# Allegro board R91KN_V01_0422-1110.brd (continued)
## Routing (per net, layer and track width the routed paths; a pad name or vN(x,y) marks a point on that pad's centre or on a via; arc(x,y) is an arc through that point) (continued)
M_MDA43: length 67.1
  TOP w0.1: 102.61,64.01 101.96,64.01 101.82,63.87 101.48,63.87 101.43,63.91 100.71,63.91 100.69,63.88 100.39,63.88 100.37,63.91 99.92,63.91 99.88,63.88 99.12,63.88 98.65,63.4 U1.F11
  TOP w0.12: v1(126.71,67.43) 126.69,67.43 126.69,67.41 126.18,67.93 126.18,70.57 126.3,70.69 127.46,70.69 127.58,70.81 127.58,71.24 127.46,71.36 124.06,71.36 123.94,71.49 123.94,72.07 124.06,72.19 124.79,72.19 124.8,72.2 124.8,72.19 126.03,72.19 126.16,72.32 126.16,72.55 126.03,72.67 124.79,72.67 124.68,72.79 124.68,73.03 124.8,73.16 125.84,73.16 125.96,73.28 125.96,73.54 125.84,73.67 124.88,73.67 124.75,73.79 124.75,74.1 124.88,74.22 126.05,74.22 126.18,74.35 126.18,74.53 126.03,74.68 124.32,74.68 124.2,74.56 124.2,73.01 124,72.8 123.79,72.8 123.52,72.53 123.52,70.83 123.1,70.41 111.98,70.41 109.54,67.98 109.54,67.92 107.47,65.86 104.77,65.86 102.91,64.01 102.61,64.01
  BOTTOM w0.12: v1(126.71,67.43) 126.69,67.43 126.69,67.41 126.37,67.41 126.25,67.52 126.25,67.74 126.24,67.75 126.24,70.56 126.63,70.96 v4(126.63,71.34) 126.63,72 126.94,72.3 130.5,72.3 131.22,73.02 132.71,73.02 132.92,73.23 132.92,73.43 133.29,73.8 133.48,73.8 133.5,73.82 133.51,73.82 133.72,74.03 133.72,74.03 133.86,74.17 U402.H7
M_MDA44: length 65.7
  TOP w0.099: 102.58,65.33 102.34,65.09 101.04,65.09 U1.A9
  TOP w0.12: v1(109.78,70.34) 107.17,67.74 107.16,67.74 107.01,67.59 105.15,67.59 102.88,65.33 102.58,65.33
  BOTTOM w0.12: 137.37,76.58 137.5,76.58 137.94,77.02 138.31,77.02 138.52,77.23 138.52,77.43 138.82,77.73 139.34,77.73 139.59,77.99 139.67,77.99 140.34,78.65 140.34,80.46 135.69,85.11 122.65,85.11 121.45,83.91 121.45,81.78 119.51,79.85 117.09,79.85 116.76,79.53 114.59,77.39 114.52,77.34 114.38,77.2 114.06,77.05 113.76,76.85 112.99,76.53 112.17,76.36 112.16,76.36 112.12,76.32 110.61,76.32 110.05,75.75 110.05,75.53 110.17,75.41 v4(110.59,75.41) 110.59,75.41 110.71,75.29 110.71,75.05 110.59,74.93 110.17,74.93 110.05,74.81 110.05,74.58 110.17,74.45 110.59,74.45 110.59,74.45 110.71,74.33 110.71,74.09 110.59,73.97 110.17,73.97 110.05,73.84 110.05,73.63 110.17,73.5 110.56,73.5 110.67,73.39 110.67,73.2 110.56,73.08 109.55,73.08 109.45,72.98 109.45,72.71 109.57,72.58 111.09,72.58 111.22,72.46 111.22,71.06 110.49,70.34 v1(109.78,70.34)
M_MDA45: length 66
  TOP w0.099: U1.C9 100.4,65.25 100.66,65.25
  TOP w0.12: 100.66,65.25 100.68,65.27 100.77,65.27 100.82,65.33 101.09,65.33 101.09,65.32 102.24,65.32 102.56,65.64 102.89,65.64 105.23,67.99 105.66,67.99 105.66,67.98 106.62,67.98 106.89,68.26 106.89,68.42 106.84,68.48 106.84,68.65 107,68.82 107.17,68.82 107.23,68.76 107.4,68.76 107.57,68.93 107.57,69.1 107.51,69.16 107.51,69.33 107.68,69.5 107.85,69.5 107.91,69.44 108.08,69.44 v4(108.25,69.61) 108.25,69.78 108.19,69.84 108.19,70.01 108.34,70.16 109.03,70.16 109.37,70.49 109.37,70.51 109.6,70.75 109.62,70.75 109.85,70.98 110.1,70.98 110.28,70.81 v1(110.3,70.81)
  BOTTOM w0.12: v1(110.3,70.81) 110.06,71.05 109.89,71.05 109.06,71.88 109.06,73.36 109.18,73.48 109.53,73.48 109.65,73.6 109.65,73.84 109.53,73.96 109.17,73.96 109.06,74.08 109.06,74.32 109.17,74.44 109.53,74.44 109.65,74.56 109.65,74.8 109.53,74.92 109.17,74.92 109.06,75.04 109.06,75.31 110.5,76.76 112.13,76.76 112.87,76.9 113.57,77.19 113.94,77.44 114.18,77.57 114.25,77.64 114.35,77.7 116.73,80.05 116.93,80.25 119.35,80.25 121.05,81.95 121.05,84.11 122.45,85.5 135.85,85.5 140.56,80.8 140.56,77.49 140.15,77.09 139.8,77.09 139.32,76.61 139.32,76.43 139.11,76.22 138.61,76.22 U402.F2
M_MDA46: length 66.6
  TOP w0.099: 103.07,66.12 105.14,68.19 ; 102.39,66.13 102.22,66.13 102.12,66.04 102.12,65.66 102,65.53 101.18,65.53 101.18,65.53 100.73,65.53 100.68,65.49 100.13,65.49 100.01,65.36 100.01,65.32 99.88,65.19 99.62,65.19 99.48,65.33 99.22,65.33 99.09,65.19 98.67,65.19 98.55,65.07 U1.F9
  TOP w0.1: 103.07,66.12 102.8,65.86 102.61,65.86 102.48,65.98 102.48,66.04 102.39,66.13
  TOP w0.12: v1(109,71.33) 108.95,71.33 108.29,70.66 108.09,70.66 107.85,70.42 107.85,70.22 107.61,69.98 107.41,69.98 107.17,69.75 107.17,69.54 106.93,69.3 106.73,69.3 106.49,69.07 106.49,68.86 v4(106.18,68.55) 106.01,68.38 105.8,68.38 105.79,68.36 105.47,68.36 105.45,68.38 105.32,68.38 105.14,68.19
  BOTTOM w0.12: v1(109,71.33) 108.85,71.33 108.59,71.58 108.59,75.41 110.33,77.15 112.09,77.15 112.76,77.28 113.39,77.54 113.82,77.83 114.1,78.01 116.63,80.5 116.77,80.64 119.19,80.64 120.66,82.11 120.66,84.29 122.27,85.89 136.01,85.89 140.95,80.96 140.95,77.32 140.57,76.95 140.57,76.72 140.78,76.52 140.78,75.96 140.17,75.35 139.81,75.35 139.75,75.41 138.6,75.41 U402.G2
M_MDA47: length 65.9
  TOP w0.099: U1.D8 100.03,66.08 100.37,66.08 100.39,66.11 100.68,66.11 100.71,66.09 101.17,66.09 101.41,66.33 102.86,66.33 105.29,68.76 105.56,68.76
  TOP w0.12: 105.56,68.76 107.82,71.03 107.89,71.03 107.94,71.07 107.96,71.07 108.03,71.14 v1(108.19,71.14)
  BOTTOM w0.12: 137.37,74.17 137.6,74.17 137.96,74.54 139.91,74.54 141.34,75.97 141.34,81.12 136.41,86.05 136.41,86.06 136.18,86.29 121.97,86.29 119.91,84.24 v4(119.91,83.21) 119.91,81.92 119.03,81.03 116.6,81.03 113.86,78.32 113.7,78.22 113.2,77.89 112.64,77.66 112.05,77.54 110.16,77.54 108.19,75.57 v1(108.19,71.14)
M_MDA48: length 67.3
  TOP w0.099: 100.74,67.14 100.55,66.94 100.38,66.94 100.19,67.13 99.94,67.13 99.78,66.97 99.78,66.72 99.65,66.6 U1.E7 ; 101.12,67.14 101.43,67.14 101.53,67.23
  TOP w0.1: 100.74,67.14 101.12,67.14
  TOP w0.12: 101.53,67.23 102.14,67.23 102.27,67.36 102.27,68.39 104.9,71.02 104.9,72.06 105.63,72.78 105.63,75.05 105.73,75.16 106.06,75.16 106.18,75.03 106.18,73.2 106.32,73.06 106.52,73.06 106.66,73.2 106.66,73.2 106.66,75.03 106.78,75.16 107.02,75.16 107.14,75.03 107.14,73.2 107.28,73.06 107.48,73.06 107.62,73.2 107.62,73.2 107.62,75.05 107.75,75.18 107.97,75.18 108.1,75.05 108.1,73.2 108.24,73.06 108.31,73.06 108.32,73.06 108.45,73.06 108.58,73.2 108.58,73.2 108.58,75.03 108.7,75.16 108.78,75.16 108.8,75.18 108.94,75.18 109.06,75.05 109.06,73.2 109.19,73.06 109.41,73.06 109.54,73.2 109.54,73.2 109.54,75.03 109.66,75.16 109.89,75.16 110.02,75.03 110.02,73.2 110.16,73.06 110.65,73.06 110.77,73.18 110.77,73.36 110.5,73.62 110.5,75.03 110.62,75.16 110.87,75.16 110.99,75.03 110.99,73.7 111.13,73.56 111.28,73.56 111.47,73.75 111.47,75.03 111.6,75.16 112.37,75.16 112.78,75.56 112.78,76.27 113.01,76.5 113.36,76.5 v4(116.82,79.96) 117.17,80.31 117.99,80.31 118.55,80.87 118.59,80.87 118.61,80.89 118.62,80.89 118.63,80.9 133.13,80.9 133.15,80.89 133.33,80.89 133.38,80.83 133.39,80.83 134.12,80.11 134.12,79.93 134.16,79.88 U401.A3
M_MDA49: length 66.6
  TOP w0.1: U1.A7 101.08,66.73 101.08,66.73 102.51,66.73 104.09,68.31
  TOP w0.12: 133.37,79.78 133.37,79.99 133.23,80.12 132.72,80.12 132.71,80.13 132.42,80.13 132.41,80.12 131.92,80.12 131.91,80.13 131.49,80.13 131.41,80.05 131.41,79.77 131.37,79.72 130.83,79.72 130.71,79.85 130.71,79.88 130.58,80 130.09,80 129.9,79.81 129.73,79.81 129.54,80 129.37,80 129.18,79.81 129.01,79.81 128.82,80 128.65,80 128.46,79.81 128.29,79.81 128.1,80 127.93,80 127.74,79.81 127.57,79.81 127.38,80 127.21,80 127.02,79.81 126.78,79.81 126.65,79.94 126.65,79.94 126.53,80.07 126,80.07 125.88,79.94 125.88,79.13 125.76,79.02 125.52,79.02 125.4,79.14 125.4,79.97 125.27,80.09 125.04,80.09 124.92,79.97 124.92,79.13 124.8,79.02 124.56,79.02 124.44,79.14 124.44,79.97 124.31,80.09 124.08,80.09 123.96,79.97 123.96,79.13 123.84,79.02 123.6,79.02 123.48,79.14 123.48,79.97 123.35,80.09 123.12,80.09 123,79.97 123,79.13 122.88,79.02 122.64,79.02 122.52,79.14 122.52,79.97 122.39,80.09 122.16,80.09 122.04,79.97 122.04,79.13 121.92,79.02 121.69,79.02 121.57,79.14 121.57,79.97 121.45,80.09 121.18,80.09 121.06,79.97 121.06,79.12 120.94,79 120.53,79 120.41,79.12 v4(120.41,79.75) 120.41,79.91 120.28,80.03 119.48,80.03 119.36,79.91 119.36,79.77 119.63,79.5 119.73,79.5 119.86,79.38 119.86,79.19 119.72,79.05 119.54,79.05 119.33,79.26 119.15,79.26 119,79.11 119,78.93 119.61,78.31 119.61,78.14 119.44,77.97 119.27,77.97 118.65,78.59 118.48,78.59 118.31,78.42 118.31,78.25 118.93,77.63 118.93,77.46 118.76,77.29 118.59,77.29 117.97,77.91 117.8,77.91 117.63,77.74 117.63,77.57 118.25,76.95 118.25,76.78 118.08,76.61 117.91,76.61 117.29,77.23 117.12,77.23 116.95,77.06 116.95,76.89 117.58,76.27 117.58,76.1 117.41,75.94 117.24,75.94 116.62,76.56 116.45,76.56 116.28,76.39 116.28,76.22 116.9,75.6 116.9,75.43 116.73,75.26 116.56,75.26 115.94,75.88 115.77,75.88 115.6,75.71 115.6,75.54 116.22,74.92 116.22,74.75 116.05,74.58 115.88,74.58 115.26,75.2 114.89,75.2 114.42,74.72 114.42,74.7 114.09,74.37 114.09,74.19 114.53,73.75 114.53,72.71 114.1,72.28 108.64,72.28 108.64,72.28 106.43,72.28 106.31,72.15 106.31,72 106.12,71.82 105.96,71.82 105.94,71.84 105.8,71.84 105.69,71.73 105.69,70.69 104.09,69.09 104.09,68.31
M_MDA50: length 67.1
  TOP w0.1: U1.C7 100.21,66.54 100.51,66.54 100.63,66.67 100.63,66.73 100.81,66.92 100.94,66.92 100.96,66.93 102.43,66.93 103.46,67.96 103.46,69.02
  TOP w0.12: 103.46,69.02 105.29,70.86 105.29,71.89 106.07,72.67 108.48,72.67 108.48,72.67 111.73,72.67 111.85,72.8 v4(111.85,73.09) 111.85,73.58 111.87,73.59 111.87,74.61 111.99,74.73 112.36,74.73 112.48,74.61 112.48,74.6 112.88,74.2 112.88,73.96 112.48,73.56 112.48,72.79 112.6,72.67 112.88,72.67 113,72.8 113,73.51 113.13,73.64 113.43,73.64 113.56,73.51 113.56,72.8 113.68,72.67 113.93,72.67 114.09,72.83 114.09,73.43 114.1,73.44 114.1,73.61 112.82,74.88 112.82,75.05 112.99,75.22 113.16,75.22 113.68,74.7 113.86,74.7 114.02,74.86 114.02,75.04 113.25,75.81 113.25,75.98 113.38,76.11 113.63,76.11 114.35,75.39 114.53,75.39 114.69,75.55 114.69,75.73 114.02,76.39 114.02,76.57 114.19,76.73 114.36,76.73 114.95,76.15 115.12,76.15 115.29,76.31 115.29,76.49 114.68,77.1 114.68,77.26 114.85,77.44 115.02,77.44 115.66,76.79 115.84,76.79 116,76.95 116,77.13 115.38,77.75 115.38,77.93 115.54,78.09 115.72,78.09 116.37,77.44 116.55,77.44 116.71,77.6 116.71,77.78 116.02,78.47 116.02,78.61 116.22,78.81 116.36,78.81 117.12,78.05 117.29,78.05 117.46,78.22 117.46,78.39 116.89,78.96 116.89,79.11 117.08,79.3 117.23,79.3 117.78,78.75 117.96,78.75 118.12,78.91 118.12,79.09 117.57,79.64 117.57,79.79 117.7,79.92 117.97,79.92 118.52,79.37 118.7,79.37 118.86,79.53 118.86,79.71 118.51,80.06 118.51,80.23 118.78,80.5 132.97,80.5 132.98,80.5 133.17,80.5 133.5,80.17 133.5,80.17 133.72,79.95 133.72,78.89 134.16,78.44 U401.C3
M_MDA51: length 67.7
  TOP w0.099: 99.34,66.28 99.48,66.28 99.48,66.29 100.28,66.29 100.3,66.3
  TOP w0.1: U1.F7 98.5,66.65 98.5,66.86 98.4,66.97 98.19,66.97 98.07,66.84 98.07,66.41 98.19,66.28 99.34,66.28 ; 108.13,71.74 108.12,71.74 107.91,71.53 107.88,71.53 107.8,71.45 107.78,71.45 107.73,71.41 107.52,71.41 107.47,71.45 107.46,71.45 107.23,71.69 107.23,71.7 107.04,71.89 106.86,71.89 106.74,71.77 106.74,71.63 107.24,71.13 107.24,70.99 107.09,70.84 106.95,70.84 106.36,71.44 106.2,71.44 106.08,71.32 106.08,71.15 106.67,70.56 106.67,70.42 106.53,70.28 106.39,70.28 106.22,70.44 106.05,70.44 105.94,70.33 105.94,70.16 106.1,70 106.1,69.85 105.96,69.71 105.82,69.71 105.61,69.93 105.46,69.93 105.32,69.79 105.32,69.65 105.54,69.43 105.54,69.29 105.4,69.15 105.26,69.15 105.04,69.36 104.9,69.36 104.76,69.22 104.76,69.08 104.97,68.86 104.97,68.72 102.78,66.53 101.33,66.53 101.09,66.28 100.81,66.28 100.79,66.31 100.31,66.31 100.3,66.3
  TOP w0.12: 108.13,71.74 108.27,71.88 114.25,71.88 114.92,72.55 114.92,74.48 115.02,74.58 115.32,74.58 115.45,74.44 115.45,74.14 115.58,74.02 116.04,74.02 119.6,77.57 119.77,77.57 120.33,77 120.51,77 120.67,77.17 120.67,77.34 120,78.01 120,78.2 v4(120.28,78.48) 120.4,78.6 120.97,78.6 121.11,78.46 121.11,77.27 121.23,77.15 121.47,77.15 121.59,77.27 121.59,77.27 121.59,78.46 121.72,78.58 121.94,78.58 122.07,78.46 122.07,77.27 122.19,77.15 122.43,77.15 122.55,77.27 122.55,77.27 122.55,78.46 122.68,78.58 122.91,78.58 123.03,78.46 123.03,77.27 123.15,77.15 123.39,77.15 123.51,77.27 123.51,77.27 123.51,78.46 123.63,78.58 123.87,78.58 123.99,78.46 123.99,77.27 124.11,77.15 124.35,77.15 124.47,77.27 124.47,77.27 124.47,78.46 124.59,78.58 124.82,78.58 124.95,78.46 124.95,77.27 125.07,77.15 125.31,77.15 125.43,77.27 125.43,77.27 125.43,78.46 125.56,78.58 125.78,78.58 125.91,78.46 125.91,77.27 126.03,77.15 126.22,77.15 126.4,77.33 126.81,77.73 129.93,77.73 130.22,78.03 131.08,78.03 131.47,78.42 131.47,78.9 131.63,79.06 131.82,79.06 132.06,78.83 132.06,78.75 132.19,78.62 133.62,78.62 133.73,78.52 133.73,78.3 133.6,78.17 133.37,78.17
M_MDA52: length 66.2
  TOP w0.12: U1.A5 101.16,68.2 102.44,69.48 102.44,69.5 102.68,69.74 102.68,70.09 102.8,70.22 103.03,70.22 103.16,70.34 103.16,70.52 103.05,70.62 102.84,70.62 102.72,70.75 102.72,70.9 102.93,71.12 103.25,71.12 103.44,71.31 103.44,71.62 103.44,72.1 104.16,72.82 104.16,77.41 104.44,77.68 104.44,77.85 104.16,78.13 104.16,78.36 104.3,78.5 104.47,78.5 104.78,78.19 104.95,78.19 107.83,81.07 107.83,81.24 107.75,81.32 107.75,81.5 107.91,81.66 108.09,81.66 108.17,81.58 108.42,81.58 110.62,83.77 112.94,83.77 113.06,83.65 113.06,83.45 113.2,83.31 113.37,83.31 113.38,83.31 113.4,83.31 113.53,83.43 113.53,83.65 113.65,83.77 113.88,83.77 114,83.65 114,82.68 114.21,82.47 114.35,82.47 114.48,82.59 114.48,83.65 114.59,83.77 114.84,83.77 114.96,83.65 114.96,82.45 114.65,82.14 114.65,81.89 114.79,81.76 114.96,81.76 115.11,81.91 115.11,81.91 115.44,82.24 115.44,83.65 115.55,83.77 115.8,83.77 115.92,83.65 115.92,83.23 116.04,83.11 116.27,83.11 116.4,83.23 116.4,83.67 116.5,83.77 134.42,83.77 134.52,83.67 134.52,83.53 134.64,83.41 134.87,83.41 135,83.53 135,83.67 135.09,83.77 135.51,83.77 135.79,83.5 135.79,83.33 v4(135.34,82.87) 135.34,82.7 135.5,82.54 135.68,82.54 136.13,82.99 136.3,82.99 136.47,82.82 136.47,82.65 136.02,82.2 136.02,82.02 136.18,81.86 136.36,81.86 136.81,82.31 136.98,82.31 137.15,82.14 137.15,81.97 136.62,81.44 136.62,81.26 136.78,81.1 136.96,81.1 137.47,81.61 137.64,81.61 138.01,81.24 138.01,81.06 137.77,80.83 137.43,80.83 137.3,80.7 137.3,80.46 137.43,80.33 137.7,80.33 137.82,80.21 137.82,79.9 137.71,79.78 137.59,79.78 137.59,79.78 137.37,79.78
M_MDA53: length 66.7
  TOP w0.1: 99.35,68.44 99.53,68.62 100.79,68.62
  TOP w0.12: U1.E5 99.35,68.44 ; 100.79,68.62 101.21,68.62 102.39,69.8 102.39,71.17 103.09,71.86 103.09,72.49 103.77,73.17 103.77,79 104.07,79.31 104.24,79.31 104.79,78.76 104.96,78.76 105.13,78.93 105.13,79.1 104.58,79.64 104.58,79.81 104.75,79.98 104.92,79.98 105.47,79.44 105.64,79.44 105.81,79.61 105.81,79.78 105.26,80.32 105.26,80.49 105.43,80.66 105.6,80.66 106.15,80.11 106.32,80.11 106.49,80.28 106.49,80.45 105.94,81 105.94,81.17 106.11,81.34 106.28,81.34 106.74,80.88 106.92,80.88 107.08,81.05 107.08,81.22 106.62,81.68 106.62,81.85 106.79,82.02 106.96,82.02 107.22,81.76 107.39,81.76 107.56,81.93 107.56,82.1 107.3,82.36 107.3,82.53 107.47,82.7 107.64,82.7 108.19,82.15 108.36,82.15 108.53,82.32 108.53,82.49 107.98,83.04 107.98,83.21 108.15,83.38 108.32,83.38 108.87,82.83 109.04,82.83 109.21,83 109.21,83.17 108.66,83.72 108.66,83.89 108.93,84.17 109.16,84.17 109.29,84.04 109.29,83.66 109.41,83.53 109.75,83.53 109.88,83.66 v4(109.88,83.95) 109.88,84.04 110,84.17 135.67,84.17 138.98,80.86 138.98,80.44 138.66,80.11 138.66,79.97 138.53,79.85 138.53,79.29 138.22,78.97 U401.B8
M_MDA54: length 66.2
  TOP w0.1: 101.73,70.28 101.72,70.27 101.72,70.27 100.81,69.37 100.8,69.37 100.58,69.16 100.58,69.05 100.45,68.92 100.23,68.92 U1.C3
  TOP w0.12: 101.73,70.28 101.86,70.41 101.86,71.08 102.82,72.05 102.82,73.16 v4(103.19,73.52) 103.38,73.71 103.38,74.09 103.25,74.21 102.6,74.21 102.47,74.09 102.47,73.8 102.35,73.67 102.07,73.67 101.94,73.8 101.94,74.57 102.07,74.69 103.25,74.69 103.38,74.82 103.38,75.19 103.25,75.32 103.25,75.32 101.42,75.32 101.31,75.42 101.31,75.7 101.4,75.79 103.24,75.79 103.38,75.93 103.38,76.2 103.25,76.33 102.82,76.33 102.69,76.45 102.69,76.69 102.82,76.81 103.25,76.81 103.25,76.81 103.38,76.94 103.38,77.21 103.25,77.33 102.88,77.33 102.76,77.46 102.76,77.69 102.88,77.81 103.25,77.81 103.38,77.94 103.38,78.28 103.14,78.51 103.14,78.66 103.38,78.9 103.38,79.16 108.77,84.56 135.84,84.56 139.46,80.93 139.56,80.93 139.8,80.69 139.8,80.35 139.32,79.87 139.32,79.55 139.41,79.45 139.59,79.45 139.62,79.42 139.75,79.42 139.87,79.3 139.87,79 139.75,78.88 139.41,78.88 139.15,78.62 139.04,78.62 138.94,78.53 138.82,78.53 138.61,78.32 138.61,78.17 138.48,78.04 138.29,78.04 138.16,78.17 U401.C8
M_MDA55: length 66.1
  TOP w0.12: U1.E1 99.48,69.94 99.48,70.09 100.44,71.06 100.62,71.06 100.8,71.22 101.18,71.22 102.28,72.32 102.28,72.73 102.16,72.86 101.72,72.86 101.53,73.04 101.53,74.65 100.92,75.27 100.92,75.69 100.8,75.81 100.6,75.81 100.48,75.69 100.48,74.92 100.35,74.8 100.17,74.8 100.05,74.92 100.05,75.89 100.22,76.05 100.22,76.06 100.34,76.18 100.34,76.21 100.38,76.26 100.38,76.5 100.5,76.62 100.75,76.62 100.86,76.5 100.86,76.31 100.98,76.18 102.12,76.18 102.25,76.31 102.25,76.54 102.12,76.66 101.42,76.66 101.3,76.79 101.3,76.96 101.35,77.02 101.35,77.02 101.48,77.14 102,77.14 v4(102.16,77.31) 102.28,77.42 102.28,77.88 102.74,78.34 102.74,79.08 108.61,84.95 136,84.95 140.12,80.83 140.12,78.43 139.74,78.06 139.67,78.06 139.34,77.73 138.31,77.73 138.02,77.73 137.81,77.52 137.81,77.28 137.69,77.15 137.49,77.15 137.37,77.28 137.37,77.38
M_MDA56: length 65
  TOP w0.1: 99.35,69.33 99.23,69.33 98.87,68.96 98.87,68.36 98.22,67.71 98.22,67.42 97.75,66.95 U1.G7
  TOP w0.12: v1(100.97,70.81) 100.95,70.83 100.54,70.83 99.7,70 99.7,69.68 99.35,69.33 ; v1(115.37,73.36) 115.41,73.33 v4(115.41,72.14) 115.41,72 115.53,71.88 116.73,71.88 116.94,72.09 116.94,72.27 117.17,72.5 117.17,72.75 117.3,72.88 117.85,72.88 118.31,73.33 118.31,73.36 118.6,73.66 118.61,73.66 119.98,75.03 121.31,75.03 121.45,75.16 126.53,75.16 126.69,75 126.69,74.28 126.57,74.17 126.57,72.42 126.69,72.3 129.18,72.3 129.43,72.55 129.43,72.79 129.72,73.08 130.11,73.08 130.13,73.11 130.98,73.11 131.01,73.14 131.83,73.14 132.51,73.82 132.71,73.82 132.92,74.03 132.92,74.23 133.22,74.53 133.62,74.53 133.97,74.17 U401.H3
  BOTTOM w0.12: v1(115.37,73.36) 114.47,73.36 114.34,73.24 114.34,72.94 114.22,72.81 114,72.81 113.88,72.94 113.88,73.31 113.72,73.47 113.39,73.47 113.27,73.34 113.27,69.13 112.7,68.56 112.7,68.56 112.47,68.33 112.47,68.33 112.29,68.16 112.12,68.16 111.95,68.33 111.7,68.33 111.57,68.2 111.57,68.03 111.78,67.82 111.78,67.65 111.61,67.48 111.44,67.48 111.39,67.53 111.09,67.53 110.96,67.41 110.96,67.16 110.98,67.14 110.98,66.84 110.81,66.67 110.54,66.67 110.41,66.8 110.41,67.14 110.29,67.27 110,67.27 109.86,67.13 109.86,66.59 110.03,66.42 110.03,66.2 109.91,66.08 109.51,66.08 109.38,66.2 109.39,67.19 109.27,67.31 109.03,67.31 108.91,67.18 108.91,66.2 108.78,66.08 108.55,66.08 108.42,66.2 108.43,67.19 108.31,67.31 108.07,67.31 107.94,67.18 107.94,66.2 107.82,66.08 107.59,66.08 107.47,66.2 107.47,67.19 107.35,67.31 107.1,67.31 106.97,67.17 106.97,66.2 106.84,66.08 106.63,66.08 106.5,66.2 106.5,68.2 106.38,68.33 104.11,68.33 101.76,70.68 101.1,70.68 v1(100.97,70.81)
M_MDA57: length 64.6
  TOP w0.099: 98.28,69.6 98.15,69.47 98.15,68.14 97.75,67.74 U1.G6
  TOP w0.12: 133.37,74.97 133.34,74.97 132.93,74.56 130.41,74.56 v4(129.69,75.28) 129.41,75.56 121.29,75.56 121.16,75.42 119.82,75.42 118.45,74.06 118.44,74.06 117.91,73.53 117.91,73.5 117.69,73.28 116.9,73.28 116.78,73.15 116.78,72.66 116.65,72.53 116.24,72.53 116.12,72.66 116.12,73.31 116.08,73.34 v1(116.08,73.36) ; 98.28,69.6 98.28,70.02 98.26,70.03 98.26,70.78 98.33,70.85 ; 98.74,71.4 99.4,72.06 100.27,72.06 v1(100.31,72.03)
  TOP w0.13: 98.74,71.4 98.33,70.99 98.33,70.85
  BOTTOM w0.12: v1(100.31,72.03) 100.31,71.78 100.79,71.3 101.72,71.3 103.62,69.4 103.79,69.4 104.05,69.66 104.22,69.66 104.39,69.49 104.39,69.32 104.13,69.06 104.13,68.89 104.3,68.72 104.84,68.72 104.96,68.84 104.96,69.53 105.09,69.66 105.32,69.66 105.44,69.53 105.44,68.84 105.56,68.72 105.8,68.72 105.92,68.84 105.92,69.45 106.05,69.58 106.25,69.58 106.4,69.42 106.4,68.84 106.52,68.72 106.55,68.72 106.55,68.72 106.78,68.72 106.9,68.59 106.9,67.8 107,67.7 107.21,67.7 107.31,67.8 107.31,68.59 107.44,68.72 107.61,68.72 107.73,68.59 107.73,67.79 107.83,67.7 108.04,67.7 108.13,67.79 108.13,68.59 108.25,68.72 108.49,68.72 108.61,68.59 108.61,67.84 108.73,67.72 108.96,67.72 109.09,67.84 109.09,68.59 109.21,68.72 109.45,68.72 109.57,68.59 109.57,67.85 109.69,67.72 109.9,67.72 110.05,67.87 110.05,68.59 110.17,68.72 110.41,68.72 110.53,68.59 110.53,67.99 110.65,67.87 110.89,67.87 111.01,67.99 111.01,68.6 111.13,68.72 112.31,68.72 112.87,69.29 112.87,73.19 112.49,73.57 112.49,74.64 112.6,74.75 112.84,74.75 112.94,74.64 112.94,73.99 113.07,73.87 113.31,73.87 113.43,73.98 113.43,74.61 113.56,74.73 113.78,74.73 113.91,74.61 113.91,73.93 114.03,73.8 115.64,73.8 v1(116.08,73.36)
M_MDA58: length 63.7
  TOP w0.099: U1.G1 97.75,70.45 97.79,70.49
  TOP w0.12: v1(117.06,74.38) 117.16,74.38 117.19,74.34 117.62,74.34 119.5,76.22 120,76.22 120,76.22 120.83,76.22 120.95,76.34 130.03,76.34 130.16,76.47 130.16,76.49 130.28,76.61 130.28,76.64 130.41,76.77 130.99,76.77 131.12,76.64 131.12,76.58 131.37,76.33 131.49,76.33 131.6,76.22 133.51,76.22 133.86,76.58 U401.E3 ; v1(101.13,72.46) 100.8,72.79 100.8,72.86 100.53,73.12 99.83,73.12 97.79,71.07 97.79,70.49
  BOTTOM w0.12: v1(101.13,72.46) 101.56,72.03 102.67,72.03 104.56,73.92 v4(104.56,74.49) 105.04,74.98 107.25,74.98 107.37,74.85 107.37,74.62 107.25,74.5 105.29,74.5 105.16,74.37 105.16,73.62 105.28,73.5 105.48,73.5 105.61,73.63 105.61,73.89 105.73,74.02 107.24,74.02 107.37,73.89 107.37,73.66 107.24,73.54 106.13,73.54 106.01,73.42 106.01,73.18 106.13,73.06 107.16,73.06 107.28,72.93 107.28,72.8 106.88,72.4 106.65,72.4 106.41,72.64 106.23,72.64 106.08,72.49 106.08,72.31 106.3,72.09 106.3,71.82 106.13,71.65 106.13,70.8 106.36,70.57 107.42,69.52 111.22,69.52 112.09,70.39 112.09,72.87 111.71,73.25 111.71,75.16 112.08,75.53 113.33,75.53 113.64,75.84 114.55,75.84 114.69,75.7 114.69,74.83 114.91,74.61 116.84,74.61 117.06,74.41 v1(117.06,74.38)
M_MDA59: length 64.1
  TOP w0.099: U1.G3 97.92,69.17 97.92,69.53 98.06,69.67 98.06,69.93 98.04,69.96 98.04,70.42
  TOP w0.12: v1(100.39,72.69) 100.38,72.69 100.35,72.71 99.73,72.71 98.04,71.01 98.04,70.42 ; 133.37,75.78 133.01,75.42 131.63,75.42 131.17,74.96 130.81,74.96 129.82,75.95 121.12,75.95 120.99,75.82 119.84,75.82 119.84,75.83 119.66,75.83 118.29,74.45 118.28,74.45 117.5,73.67 116.87,73.67 116.71,73.83 116.65,73.83 116.63,73.84 v1(116.6,73.84)
  BOTTOM w0.12: v1(100.39,72.69) 100.72,72.36 100.72,72.18 101.32,71.58 101.89,71.58 102.07,71.4 102.24,71.4 102.48,71.64 102.83,71.64 102.84,71.65 102.85,71.65 102.92,71.58 102.92,71.4 102.58,71.06 102.58,70.89 102.75,70.72 102.92,70.72 103.37,71.18 103.55,71.18 103.71,71.01 103.71,70.84 103.26,70.38 103.26,70.21 103.41,70.06 104.06,70.06 104.18,70.18 104.18,71.52 104.06,71.64 103.35,71.64 103.23,71.76 103.23,72 103.35,72.12 104.06,72.12 104.18,72.24 104.18,72.98 104.35,73.15 104.56,73.15 104.68,73.03 104.68,70.18 104.81,70.06 105.01,70.06 105.13,70.18 105.13,72.92 105.26,73.05 105.49,73.05 105.62,72.92 105.62,72.92 105.62,70.18 105.74,70.06 106.32,70.06 107.26,69.12 111.38,69.12 112.48,70.22 112.48,73.03 112.1,73.41 112.1,74.83 112.41,75.14 113.49,75.14 113.57,75.22 v4(114.06,75.22) 114.14,75.22 114.3,75.07 114.3,74.37 114.44,74.22 115.06,74.22 115.09,74.19 116.34,74.19 116.58,73.95 116.58,73.89 116.6,73.88 v1(116.6,73.84)
M_MDA60: length 68.1
  TOP w0.099: 96.52,70.85 96.51,70.84 96.51,70.18 96.66,70.03 96.66,70.02 96.66,70.02 96.66,69.59 96.62,69.55 96.62,69.29 96.7,69.2 96.7,68.81 96.66,68.77 96.66,68.75 96.62,68.72 96.62,68.61 96.47,68.45 96.47,67.97 96.37,67.86 95.81,67.86 95.69,67.74 95.69,67.53 95.81,67.4 U1.J6
  TOP w0.12: 137.37,75.78 137.6,75.78 137.81,75.99 138.04,76.22 138.37,76.22 138.49,76.34 138.49,76.4 138.52,76.43 138.52,76.72 138.49,76.75 138.49,76.89 138.62,77.02 139.11,77.02 139.16,77.06 139.7,77.06 139.73,77.09 139.79,77.09 139.87,77.17 139.93,77.17 140.18,77.41 140.18,77.61 140.38,77.81 140.38,81.13 136.16,85.34 108.36,85.34 102.11,79.09 102.11,78.92 102.35,78.68 102.35,78.5 102.19,78.34 102.01,78.34 101.77,78.58 101.6,78.58 101.43,78.41 101.43,78.24 101.68,77.99 101.68,77.82 101.52,77.66 101.34,77.66 101.09,77.9 100.92,77.9 100.75,77.73 100.75,77.57 100.96,77.36 100.96,77.18 100.8,77.02 100.62,77.02 100.41,77.23 100.24,77.23 99.96,76.95 99.96,76.42 99.95,76.41 99.02,75.47 99.02,75.47 98.62,75.06 98.61,75.06 97.66,74.12 97.66,73.8 v4(97.56,73.7) 97.07,73.21 97.07,71.4 96.52,70.85
M_MDA61: length 67.1
  TOP w0.099: 96.49,72.55 96.1,71.24 96.1,69.85 U1.J1
  TOP w0.12: 137.37,74.17 137.12,74.17 136.99,74.3 136.99,74.5 137.12,74.62 138,74.62 138.01,74.61 138.31,74.61 138.48,74.78 138.49,74.78 138.61,74.91 138.61,75.12 138.9,75.41 139.75,75.41 139.81,75.35 139.87,75.35 139.88,75.34 140.24,75.34 140.5,75.6 140.66,76.02 141.16,76.77 141.16,81.45 136.49,86.13 108.01,86.13 97.94,76.05 97.84,75.94 97.34,75.44 97.34,74.91 96.49,74.05 96.49,72.55
M_MDA62: length 67.6
  TOP w0.099: U1.J3 95.87,69.6 95.87,69.61 95.84,69.66 95.84,70 95.89,70.16 95.89,71.51 96.08,73.06 96.08,73.17
  TOP w0.12: v4(96.67,75.33) 97.55,76.2 99.26,78.22 107.85,86.53 109.39,86.54 110.11,86.54 136.65,86.52 141.55,81.62 141.58,76.83 141.52,76.62 140.89,75.44 140.4,74.95 140.2,74.8 139.71,74.53 139.38,74.54 139.38,74.54 138.93,74.55 138.21,74.19 U401.H8 ; 96.08,73.17 96.08,74
  TOP w0.13: v4(96.67,75.33) 96.12,74.31 96.08,74
M_MDA63: length 67.5
  TOP w0.099: 96.31,70.94 96.31,70.08 96.47,69.93 96.47,69.68 96.41,69.63 96.41,69.62 96.28,69.48 96.28,69.31 96.47,69.13 96.47,68.87 96.28,68.69 96.02,68.69 95.91,68.79 95.79,68.79
  TOP w0.1: U1.J5 96.02,68.07 95.84,68.07 95.75,68.16 95.75,68.17 95.66,68.25 95.66,68.67 95.79,68.79
  TOP w0.12: U401.F8 138.16,75.56 138.29,75.44 138.48,75.44 138.61,75.56 138.61,76.1 138.72,76.2 139.87,76.2 139.93,76.27 140.13,76.27 140.38,76.51 140.43,76.51 140.63,76.71 140.63,76.95 140.49,77.08 140.49,77.29 140.65,77.44 140.65,77.53 140.77,77.65 140.77,81.29 136.32,85.73 108.19,85.73 99.31,76.85 99.31,76.68 99.41,76.58 99.41,76.42 99.24,76.25 99.07,76.25 98.97,76.34 98.8,76.34 98.62,76.16 98.62,75.8 98.39,75.57 98.28,75.57 v4(98.17,75.46) 97.92,75.46 97.74,75.28 97.74,74.74 96.83,73.84 96.83,72.22 96.59,71.98 96.59,71.77 96.67,71.68 96.67,71.45 96.31,71.09 96.31,70.94
M_QSA0: length 64.6
  TOP w0.1: 97.46,47.95 97.47,47.97 97.47,48.43 97.45,48.45 97.45,48.75 97.57,48.87 97.57,49.12 97.43,49.26 97.43,49.32 U1.H28
  TOP w0.12: v1(98.81,45.2) 98.81,45.51 98.59,45.73 98.59,46.06 97.38,47.28 97.38,47.8 97.46,47.88 97.46,47.95 ; v1(116.78,36.09) 116.83,36.09 116.89,36.15 123.87,36.15 125.63,34.38 133.72,34.38 135.47,36.12 135.47,39.6 135.59,39.73 136,39.73 136.12,39.85 136.12,40.15 136,40.27 135.71,40.27 135.59,40.4 135.59,40.84 135.71,40.96 136.28,40.96 136.4,40.84 136.4,40.7 136.53,40.58 136.9,40.58 137.13,40.81 137.37,40.81
  BOTTOM w0.12: v1(116.78,36.09) 116.72,36.15 116.72,36.53 116.34,36.92 116.13,36.92 116,36.8 116,36.2 115.88,36.08 115.52,36.08 115.39,36.2 115.39,36.95 115.69,37.25 115.69,37.56 115.31,37.94 115.02,37.94 114.85,37.77 114.85,35.75 115.14,35.46 115.14,35.29 114.88,35.03 114.71,35.03 114.34,35.41 114.17,35.41 113.91,35.16 113.91,34.99 114.26,34.65 114.26,34.46 114.14,34.34 110.48,34.34 109.37,35.45 109.37,35.45 108.52,36.31 108.52,36.87 108.51,36.87 108.51,36.97 106.59,38.89 104.4,38.89 99.53,43.76 v4(99.53,44.21) 99.27,44.47 99.27,44.78 98.85,45.2 v1(98.81,45.2)
M_QSA1: length 66.7
  TOP w0.12: U202.C7 134.16,38.59 134.53,38.95 134.53,39.53 134.62,39.62 134.95,39.62 135.05,39.52 135.05,38.55 134.95,38.45 134.7,38.45 134.6,38.35 134.6,38 134.7,37.9 134.9,37.9 135,37.8 135,36.34 133.54,34.88 133.51,34.88 133.5,34.87 131,34.87 130.99,34.87 129.85,34.87 129.84,34.87 125.97,34.87 124.21,36.64 116.99,36.64 116.64,36.63 116.58,36.58 116.58,36.58 116.29,36.28 116.29,35.88 116.66,35.52 116.66,35.34 116.53,35.22 115.47,35.22 115.19,35.5 115.19,35.85 115.27,35.94 115.66,35.94 115.78,36.06 115.78,36.31 115.66,36.44 115.44,36.44 115.31,36.56 115.31,38.6 115.49,38.78 115.7,38.78 115.83,38.9 115.83,39.74 115.7,39.87 115.45,39.87 115.33,39.74 115.33,39.31 115.2,39.18 114.98,39.18 114.83,39.34 114.83,39.62 114.7,39.75 114.42,39.75 113.22,40.95 112.82,40.95 110.79,40.95 110.24,41.5 109.95,41.79 108.55,41.79 107.66,40.89 107.49,40.89 107.39,41 107.39,41.91 107.14,42.16 104.85,42.16 104.73,42.28 104.73,44.08 104.85,44.2 105.1,44.2 105.25,44.05 105.25,42.8 105.35,42.7 106,42.7 106.1,42.8 106.1,43.15 106,43.25 105.85,43.25 105.75,43.35 105.75,43.9 105.85,44 v4(106,44) 106.1,44.1 106.1,44.57 105.97,44.69 104.72,44.69 104.59,44.82 104.59,45.16 104.72,45.28 105.41,45.28 105.55,45.41 105.55,45.77 105.41,45.9 104.86,45.9 104.73,46.02 104.73,46.71 103.27,48.18 103.27,48.2 103.26,48.21 103.26,48.47 101.53,50.2 100.29,50.2 100.15,50.34 U1.C27
M_QSA2: length 65.8
  TOP w0.099: U1.A23 100.95,53.8 102.42,53.8
  TOP w0.12: 102.42,53.8 103.32,53.8 105.04,52.08 108.72,52.08 109.98,50.81 109.98,50.03 112.86,47.15 112.87,47.15 113,47.01 113.34,47.01 113.38,47.05 v1(113.48,47.05)
  BOTTOM w0.12: v1(113.48,47.05) 113.48,46.97 113.6,46.84 113.69,46.84 113.82,46.72 113.82,46.7 113.97,46.55 113.97,45.44 113.98,45.43 113.98,45.16 114.09,45.05 114.11,45.05 114.13,45.03 114.16,45.03 114.19,45.01 114.48,45.01 114.58,45.11 114.58,45.43 114.7,45.55 115.06,45.55 115.18,45.43 115.18,44.58 115.44,44.33 115.66,44.33 115.78,44.45 115.78,46.26 115.91,46.38 116.25,46.38 116.37,46.27 116.37,46.26 116.37,44.35 116.16,44.15 116.16,43.9 116.28,43.78 116.28,43.78 116.49,43.58 v4(116.84,43.58) 116.97,43.7 116.97,46.26 117.09,46.38 117.36,46.38 117.48,46.26 117.48,43.87 117.61,43.74 117.98,43.74 118.1,43.87 118.1,46.26 118.23,46.38 118.56,46.38 118.69,46.26 118.69,46.04 118.69,46.04 118.69,43.48 120.09,42.08 120.1,42.08 120.67,41.51 120.67,41.5 127.6,34.57 133.66,34.57 134.62,35.53 134.62,35.53 135.23,36.14 135.23,40.43 134.83,40.83 134.18,40.83 U201.F3
M_QSA3: length 67.1
  TOP w0.099: 101.78,57.42 101.77,57.41 101.43,57.41 101.27,57.5 101.25,57.52 100.72,57.52 100.68,57.48 99.89,57.48 99.88,57.48 99.87,57.48 99.75,57.35 99.75,57.12 99.62,57 U1.E19
  TOP w0.1: 101.78,57.42 101.98,57.42
  TOP w0.12: v1(117.35,50.38) 117.41,50.45 117.42,50.45 117.55,50.58 117.55,51.17 117.44,51.28 117.44,51.3 117.19,51.54 117.19,51.93 117.43,52.17 117.43,52.29 112.53,57.19 105.79,57.19 105.56,57.42 101.99,57.42 101.98,57.42
  BOTTOM w0.12: v1(117.35,50.38) 116.73,49.77 116.73,49.16 116.38,48.81 115.73,48.81 115.6,48.69 v4(115.6,48.37) 115.6,48.27 115.48,48.15 115.03,48.15 115.03,48.14 113.42,48.14 112.99,47.72 112.99,44.73 113.52,44.25 113.7,44.16 114.3,43.86 114.34,43.86 115,43.4 115.17,43.28 116.55,42.33 117.27,41.94 123.87,35.55 125.25,35.55 127.2,33.59 134.06,33.59 136.28,35.81 136.28,38.12 136.38,38.22 136.42,38.22 136.57,38.37 136.57,38.48 136.59,38.49 136.59,38.84 136.46,38.96 136.18,38.96 136.06,39.09 136.06,39.66 136.18,39.78 136.7,39.78 137,39.48 137,39.06 137.22,38.85 137.26,38.85 137.37,38.75 137.37,38.41
M_QSA4: length 67.1
  TOP w0.099: 102.61,60.96 102.29,60.64 101.53,60.64 101.51,60.66
  TOP w0.1: U1.E15 99.63,60.48 99.97,60.48 100.17,60.69 100.69,60.69 100.72,60.73 101.44,60.73 101.51,60.66
  TOP w0.12: v1(118.44,64.59) 118.44,64.71 118.27,64.89 117.47,64.89 117.34,65.02 117.34,65.87 117.22,65.99 116.87,65.99 116.74,65.86 116.74,64.63 116.62,64.5 116.23,64.5 116.11,64.63 116.11,65.78 115.98,65.91 115.57,65.91 115.44,65.78 115.44,64.02 115.57,63.89 115.78,63.89 115.89,63.77 115.89,63.41 115.78,63.29 115.59,63.29 115.47,63.17 115.47,62.11 115.42,62.06 115.42,62.06 115.13,61.77 115.13,61.77 114.84,61.48 103.13,61.48 102.61,60.96
  BOTTOM w0.12: U402.C7 134.16,77.97 134.19,77.95 134.19,77.87 134.35,77.7 135.09,77.7 135.22,77.83 135.22,79.82 133.54,81.49 125.08,81.49 v4(124.88,81.3) 124.88,80.37 121.66,77.14 121.66,73.8 121.23,73.38 119.66,73.38 117.17,70.89 116.09,70.89 115.89,70.69 115.89,64.81 115.89,64.81 115.89,64.64 115.97,64.56 118.38,64.56 118.41,64.59 v1(118.44,64.59)
M_QSA5: length 66.3
  TOP w0.099: 102.06,64.64 101.84,64.64 101.81,64.67 101.48,64.67 101.3,64.49 101.18,64.49 101.17,64.47 100.73,64.47 100.72,64.49 100.71,64.49 100.68,64.51 100.41,64.51 100.37,64.47 100.02,64.47 U1.D10
  TOP w0.12: v1(120.91,73.86) 121.23,73.86 121.75,74.39 121.75,74.56 121.88,74.68 122.36,74.68 122.48,74.56 122.48,73.97 122.6,73.86 122.96,73.86 123.08,73.97 123.08,74.56 123.2,74.68 123.59,74.68 123.72,74.55 123.72,73.41 123.59,73.29 122.77,73.29 122.65,73.16 122.65,72.81 122.77,72.69 122.91,72.69 123.03,72.56 123.03,72.21 122.91,72.09 122.58,72.09 122.39,71.9 122.39,71.61 122.51,71.49 122.9,71.49 123.03,71.36 123.03,71.03 122.9,70.9 111.78,70.9 107.25,66.38 106.5,66.38 106.49,66.38 106.23,66.38 106.15,66.46 105.95,66.46 105.67,66.73 105.07,66.73 102.96,64.63 102.87,64.63 102.74,64.5 102.74,64.4 102.62,64.28 102.31,64.28 102.19,64.39 102.19,64.52 102.06,64.64
  BOTTOM w0.12: 120.62,76.04 120.62,75.63 120.53,75.55 120.53,74.69 120.53,74.68 120.53,74.25 v1(120.91,73.86) ; 120.62,76.04 120.62,77.49 123.9,80.77 123.9,82.25 124.21,82.55 133.85,82.55 136.24,80.17 136.24,76.78 135.96,76.5 135.96,76.17 136.36,75.77 137.35,75.77 137.37,75.78 ; 120.62,76.04 v4(120.6,76.04)
M_QSA6: length 66.9
  TOP w0.1: U1.D6 99.75,67.59 99.88,67.72 100.69,67.72 100.75,67.65 100.99,67.65 101,67.66 101.2,67.66 101.48,67.94 101.52,67.94 101.75,68.17 101.75,68.19 101.75,68.2
  TOP w0.12: 137.37,78.17 137.37,77.84 137.26,77.74 137.22,77.74 137.01,77.53 136.6,77.53 136.48,77.66 136.48,78.03 136.61,78.16 136.84,78.16 136.97,78.28 136.97,78.56 136.84,78.69 136.61,78.69 136.48,78.81 136.48,78.88 136.46,78.9 136.46,79.94 136.41,80 136.41,80.19 133.84,82.77 117.42,82.77 117.35,82.76 115.97,81.38 v4(115.97,80.89) 115.97,80.48 115.5,80.02 115.5,79.33 113.46,77.29 113.46,77.29 113.16,76.99 112.41,76.99 112.29,76.86 112.29,75.77 112.17,75.64 111.8,75.64 111.69,75.75 111.69,76.91 111.59,77 111.19,77 111.09,76.91 111.09,75.76 110.97,75.64 110.61,75.64 110.49,75.77 110.49,76.81 110.37,76.94 110.16,76.94 109.89,76.67 109.89,75.76 109.77,75.64 109.41,75.64 109.29,75.77 109.29,76.78 109.16,76.91 109.03,76.91 108.69,76.56 108.69,75.76 108.57,75.64 108.21,75.64 108.09,75.77 108.09,76.8 107.97,76.92 107.83,76.92 107.49,76.58 107.49,75.76 107.37,75.64 107.01,75.64 106.89,75.77 106.89,76.91 106.77,77.03 106.56,77.03 106.29,76.77 106.29,75.76 106.17,75.64 105.81,75.64 105.69,75.77 105.69,76.88 105.42,77.15 105.29,77.15 105.14,77 105.14,72.98 104.41,72.26 104.41,71.22 103.93,70.73 103.93,70.36 101.76,68.2 101.75,68.2
M_QSA7: length 64.4
  TOP w0.099: U1.G5 97.43,68.52 97.43,69.13 97.46,69.17 97.46,69.63 97.43,69.66 97.43,69.94 97.53,70.04 97.53,70.1
  TOP w0.12: 100.01,74.2 v1(100.01,74.31) ; 98.98,73.84 97.53,72.4 97.53,70.1 ; v1(118.75,82.26) 118.81,82.2 118.81,81.91 118.94,81.78 133.44,81.78 135.43,79.8 135.43,77.03 134.26,75.86 134.25,75.86 U401.F3
  TOP w0.13: 100.01,74.2 99.66,73.84 98.98,73.84
  BOTTOM w0.12: v1(118.75,82.26) 116.81,84.21 110,84.21 108.38,82.58 108.38,82.58 108.09,82.29 108.09,79.77 108.06,79.75 108.06,77.7 107.94,77.58 107.67,77.58 107.55,77.7 107.55,78.28 107.45,78.38 107.09,78.38 106.97,78.26 106.97,77.69 106.84,77.56 106.5,77.56 106.37,77.69 106.37,78.26 106.25,78.38 105.89,78.38 105.77,78.26 105.77,77.69 105.64,77.56 105.3,77.56 105.17,77.69 105.17,78.26 105.05,78.38 104.7,78.38 104.69,78.37 104.66,78.37 104.54,78.25 104.54,77.66 104.41,77.53 104.03,77.53 103.9,77.66 103.9,78.25 103.78,78.38 103.44,78.38 103.31,78.25 v4(103.31,77.92) 103.31,77.75 103.19,77.62 102.4,77.62 101.91,77.14 101.91,76.49 101.41,76 99.3,76 99.13,75.83 99.13,75.19 v1(100.01,74.31)
M_QSA#0: length 64.9
  TOP w0.099: 97.28,48.91 97.28,49.12 97.28,49.12
  TOP w0.1: 97.28,48.91 97.28,48.87 97.23,48.83 97.23,48.38 97.28,48.34 97.28,48.06 97.16,47.95 97.16,47.12 ; U1.H27 96.95,50.26 96.62,49.93 96.62,49.67 96.82,49.48 96.94,49.48 97.22,49.19 97.22,49.18 97.28,49.12
  TOP w0.12: 137.37,41.62 137.37,41.35 137.73,40.99 137.73,40.66 137.51,40.45 137.27,40.45 135.97,39.15 135.97,35.92 133.93,33.89 131.4,33.89 131.39,33.88 129.45,33.88 129.44,33.89 126.85,33.89 126.85,33.89 125.43,33.89 123.67,35.66 117.73,35.66 v1(117.66,35.59) ; 97.16,47.12 97.87,46.41 97.87,46.24 98.18,45.93 98.18,45.91 98.19,45.91 v1(98.19,45.9)
  BOTTOM w0.12: v1(117.66,35.59) 117.66,35.01 118.01,34.66 118.04,34.66 118.65,34.05 118.65,33.03 118.53,32.91 118.12,32.91 118,33.03 118,34.01 117.88,34.13 117.5,34.13 117.37,34.01 v4(117.37,33.24) 117.37,33.03 117.25,32.91 116.75,32.91 116.62,33.03 116.62,33.73 116.5,33.85 116.41,33.85 116.4,33.85 110.28,33.85 108.03,36.11 108.03,36.66 107.06,37.63 107.06,37.63 106.29,38.4 104.31,38.4 98.47,44.24 98.47,44.98 98.39,45.05 98.39,45.77 98.27,45.9 v1(98.19,45.9)
M_QSA#1: length 66.4
  TOP w0.12: U1.A27 100.95,50.52 101.04,50.43 101.61,50.43 105.33,46.71 105.33,46.46 105.46,46.34 105.5,46.34 105.91,45.92 105.91,45.31 106.04,45.18 106.47,45.18 106.59,45.05 106.59,42.66 106.72,42.54 107.04,42.54 107.16,42.66 107.16,44.23 107.29,44.35 107.66,44.35 107.79,44.23 107.79,42.09 107.91,41.97 108.16,41.97 108.29,42.09 108.29,44.17 108.39,44.27 108.63,44.27 108.82,44.08 108.82,43.38 108.95,43.25 109.23,43.25 109.33,43.35 109.33,43.77 109.45,43.89 109.61,43.89 110.22,43.28 110.22,43.05 109.97,42.8 108.9,42.8 108.8,42.7 108.8,42.4 108.9,42.3 110.23,42.3 110.62,42.69 110.81,42.69 111.07,42.43 111.07,42.26 110.79,41.98 110.79,41.64 111,41.44 113.42,41.44 113.63,41.23 113.99,41.23 114.19,41.43 114.45,41.43 114.55,41.33 114.55,41.1 114.25,40.8 114.25,40.6 114.65,40.2 114.9,40.2 115,40.3 115,41.35 115.08,41.43 115.35,41.43 115.45,41.33 115.45,40.3 115.55,40.2 115.8,40.2 115.9,40.3 115.9,41.35 115.98,41.43 116.25,41.43 116.25,41.43 116.37,41.31 116.37,40.73 116.5,40.61 116.8,40.61 116.92,40.48 116.92,40.08 116.8,39.95 v4(116.47,39.95) 116.35,39.83 116.35,38.69 116.22,38.56 116,38.56 115.87,38.44 115.87,38.2 116,38.07 116.22,38.07 116.35,37.95 116.35,37.7 116.25,37.6 115.9,37.6 115.8,37.5 115.8,36.83 115.89,36.74 116.06,36.74 116.44,37.12 124.41,37.12 126.18,35.35 133.31,35.35 134.65,36.69 134.65,37.41 134.44,37.62 134.16,37.62
M_QSA#2: length 66.1
  TOP w0.099: 102.07,53.5 101.97,53.59 101.2,53.59 101.09,53.48 100.81,53.48 100.76,53.53 100.72,53.53 U1.C23
  TOP w0.12: v1(113.48,46.35) 113.47,46.35 113.44,46.31 113,46.31 109.69,49.63 109.67,49.63 109.55,49.76 109.55,49.77 109.49,49.83 109.49,50.61 108.52,51.59 104.84,51.59 102.92,53.5 102.07,53.5
  BOTTOM w0.12: 134.16,41.62 134.28,41.62 134.41,41.74 134.41,42.05 134.53,42.17 134.71,42.17 134.83,42.05 134.83,41.73 135.07,41.48 135.07,41.3 135.2,41.18 135.59,41.18 135.72,41.05 135.72,35.94 134.83,35.05 134.82,35.05 133.85,34.08 127.4,34.08 125.02,36.46 124.85,36.46 124.37,35.98 124.2,35.98 123.95,36.24 123.95,36.41 124.43,36.88 124.43,37.05 124.17,37.31 124,37.31 123.52,36.83 123.35,36.83 123.1,37.09 123.1,37.25 123.58,37.73 123.58,37.9 123.32,38.16 123.15,38.16 122.68,37.68 122.51,37.68 122.25,37.93 122.25,38.1 122.73,38.58 122.73,38.75 122.47,39.01 122.3,39.01 121.83,38.53 121.66,38.53 121.4,38.78 121.4,38.95 121.88,39.43 121.88,39.6 121.63,39.85 121.46,39.85 120.98,39.38 120.81,39.38 120.55,39.63 120.55,39.8 121.03,40.28 121.03,40.45 120.78,40.7 120.61,40.7 120.13,40.22 119.96,40.22 119.71,40.48 119.71,40.65 120.18,41.13 120.18,41.31 119.9,41.59 119.76,41.59 119.35,41.18 119.01,41.18 118.83,41.36 118.83,41.53 119.22,41.91 119.22,42.15 118.91,42.45 118.73,42.45 v4(118.42,42.14) 118.21,41.93 118.04,41.93 117.78,42.2 117.78,42.36 118.22,42.81 118.22,43.08 118.06,43.24 117.78,43.24 117.29,42.76 116.79,42.76 115.45,43.68 115.28,43.8 114.48,44.36 114.37,44.36 113.97,44.56 113.91,44.59 113.8,44.65 113.48,44.97 v1(113.48,46.35)
M_QSA#3: length 66.7
  TOP w0.099: U1.C19 100.44,57.28 100.78,57.28 100.81,57.32 101.09,57.32 101.21,57.2 101.76,57.2 101.78,57.2
  TOP w0.1: 101.78,57.2 103.37,57.2
  TOP w0.12: 103.37,57.2 103.55,57.03 105.52,57.03 105.84,56.71 111.59,56.71 111.94,56.35 112.11,56.35 112.29,56.54 112.46,56.54 112.63,56.37 112.63,56.2 112.45,56.01 112.45,55.85 112.62,55.68 112.79,55.68 112.97,55.86 113.14,55.86 113.31,55.69 113.31,55.52 113.13,55.34 113.13,55.17 113.3,55 113.47,55 113.65,55.18 113.82,55.18 113.99,55.01 113.99,54.84 113.81,54.66 113.81,54.49 113.98,54.32 114.15,54.32 114.33,54.5 114.5,54.5 114.67,54.33 114.67,54.16 114.49,53.98 114.49,53.81 114.66,53.64 114.83,53.64 115.01,53.82 115.18,53.82 115.35,53.65 115.35,53.48 115.16,53.3 115.16,53.13 115.33,52.96 115.5,52.96 115.69,53.14 115.85,53.14 116.02,52.97 116.02,52.8 115.84,52.62 115.84,52.45 116.01,52.28 116.18,52.28 116.36,52.46 116.53,52.46 116.7,52.29 116.7,52.07 116.5,51.86 116.5,51.41 116.69,51.23 116.82,51.23 116.94,51.1 116.94,50.73 v1(116.62,50.41)
  BOTTOM w0.12: 137.37,37.62 137.16,37.62 137.15,37.6 136.98,37.6 136.79,37.41 136.79,35.63 134.28,33.12 134.27,33.12 134.25,33.1 127,33.1 125.17,34.93 v4(124.5,34.93) 123.81,34.93 116.97,41.55 116.29,41.92 114.89,42.88 114.23,43.35 113.56,43.68 113.18,43.72 112.5,44.39 112.5,47.82 113.32,48.63 114.82,48.63 115.02,48.82 115.02,48.82 115.5,49.3 116.17,49.3 116.4,49.52 116.4,50.19 v1(116.62,50.41)
M_QSA#4: length 66.8
  TOP w0.099: 101.35,60.52 101.43,60.44 102.56,60.44 102.69,60.58
  TOP w0.1: 101.35,60.52 101.34,60.52 100.81,60.52 100.7,60.41 100.37,60.41 U1.C15
  TOP w0.12: v1(119.14,64.55) 119.14,64.47 118.74,64.07 118.19,64.07 117.95,64.31 117.95,64.31 117.86,64.4 117.37,64.4 117.27,64.3 117.27,64.12 117.95,63.44 117.95,63.27 117.69,63.02 117.52,63.02 116.82,63.72 116.64,63.72 116.39,63.48 116.39,63.3 117.1,62.59 117.1,62.42 116.84,62.17 116.67,62.17 116.3,62.54 116.08,62.54 115.95,62.41 115.95,62.14 116.06,62.04 116.12,62.04 116.25,61.92 116.25,61.58 115.71,61.03 103.15,61.03 102.69,60.58
  BOTTOM w0.12: v1(119.14,64.55) 119.22,64.63 119.22,64.98 119.1,65.11 118.64,65.11 118.41,65.34 118.41,65.64 118.28,65.76 117.48,65.76 117.37,65.64 117.37,65.17 117.25,65.05 116.59,65.05 116.38,65.26 116.38,66.2 116.5,66.32 v4(116.91,66.32) 117.59,66.32 117.72,66.44 117.72,66.8 117.59,66.92 116.5,66.92 116.38,67.04 116.38,67.4 116.5,67.52 117.57,67.52 117.7,67.65 117.7,68 117.59,68.12 116.48,68.12 116.38,68.22 116.38,70.3 116.48,70.39 117.38,70.39 119.87,72.89 121.44,72.89 122.14,73.59 122.14,74.24 122.15,74.24 122.15,76.95 125.37,80.17 125.37,80.56 125.81,81.01 133.45,81.01 134.53,79.93 134.53,79.34 U402.B7
M_QSA#5: length 66.3
  TOP w0.099: U1.E9 99.68,64.67 99.94,64.67 99.94,64.67 100.28,64.67 100.32,64.72 100.77,64.72 100.77,64.71 100.78,64.71 100.81,64.67 101.09,64.67 101.3,64.89 102.63,64.89 102.66,64.92
  TOP w0.12: v1(121.16,74.53) 121.13,74.5 120.98,74.5 120.95,74.48 120.15,74.48 119.77,74.1 119.77,73.65 119.64,73.53 119.16,73.53 118.92,73.28 118.92,73.03 119.05,72.9 119.64,72.9 119.77,72.78 119.77,72.66 120,72.42 121.72,72.42 121.85,72.29 121.85,71.52 121.72,71.39 120.77,71.39 120.65,71.51 v4(120.65,71.69) 120.65,71.81 120.53,71.93 120.17,71.93 120.05,71.81 120.05,71.51 119.93,71.39 119.44,71.39 119.32,71.51 119.32,72.17 119.19,72.3 118.84,72.3 118.72,72.17 118.72,71.51 118.6,71.39 118.24,71.39 118.12,71.51 118.12,72.19 118,72.31 117.68,72.31 117.52,72.16 117.52,71.51 117.4,71.39 111.57,71.39 107.44,67.25 107.36,67.25 107.12,67 107.01,67 107,67 106.98,67 106.88,67.1 105.11,67.1 102.94,64.92 102.66,64.92
  BOTTOM w0.12: v1(121.16,74.53) 121.16,74.73 121.16,74.74 121.16,77.34 124.31,80.5 124.31,81.73 124.62,82.03 133.69,82.03 135.76,79.95 135.76,76.82 135.64,76.7 134.71,76.7 134.58,76.58 134.58,76.22 134.71,76.1 135.44,76.1 135.56,75.97 135.56,75.3 135.91,74.95 136.62,74.95 136.75,74.82 137.21,74.82 137.37,74.97
M_QSA#6: length 66.4
  TOP w0.099: U1.C5 100.15,68.31 100.25,68.42 100.53,68.42 100.62,68.31 100.62,68.06 100.83,67.86 101.11,67.86 102.66,69.41
  TOP w0.12: 102.66,69.41 103.66,70.4 103.66,71.15 103.93,71.42 103.93,72.17 104.65,72.9 104.65,77.2 105.27,77.82 105.44,77.82 105.94,77.33 106.16,77.33 106.39,77.55 106.39,77.73 105.87,78.25 105.87,78.42 106.06,78.61 106.44,78.61 106.52,78.69 106.52,79.07 106.76,79.31 106.94,79.31 107.07,79.19 107.07,77.45 107.19,77.33 107.54,77.33 107.67,77.45 107.67,79.33 107.54,79.45 107.53,79.45 107.41,79.58 107.41,79.95 108.23,80.78 108.48,80.78 108.61,80.66 108.61,80.24 108.49,80.12 108.39,80.12 108.27,79.99 108.27,79.66 108.38,79.55 108.73,79.55 108.86,79.42 108.86,79.19 108.73,79.06 108.39,79.06 108.27,78.94 108.27,77.44 108.38,77.33 108.76,77.33 108.87,77.44 108.87,78.52 108.99,78.64 109.34,78.64 109.47,78.52 109.47,77.46 109.59,77.33 109.87,77.33 109.99,77.46 109.99,77.69 110.12,77.81 110.45,77.81 110.58,77.69 110.58,77.62 110.7,77.5 112.97,77.5 115.01,79.53 115.01,81.12 116.1,82.21 v4(116.1,82.43) 116.44,82.77 116.66,82.77 117.15,83.25 134.04,83.25 136.9,80.39 136.9,80.36 136.95,80.31 136.95,79.1 137.07,78.97 137.37,78.97
M_QSA#7: length 64.5
  TOP w0.099: 97.32,72.5 97.32,70.11 97.23,70.02 97.23,69.58 97.26,69.54 97.26,69.26 97.19,69.18 97.19,68.84 U1.H4
  TOP w0.12: 97.32,72.5 97.32,72.61 v1(99.13,74.42) ; v1(119.45,82.28) 133.64,82.28 135.92,80 135.92,79.72 135.93,79.71 135.93,76.96 134.16,75.2 U401.G3
  BOTTOM w0.12: v1(119.45,82.28) 119.43,82.28 117.01,84.69 109.55,84.69 107.38,82.53 107.38,79.02 107.26,78.89 106.85,78.89 106.72,79.02 106.72,79.71 106.73,79.71 106.61,79.83 106.25,79.83 106.12,79.71 106.12,79.02 106,78.89 105.65,78.89 105.53,79.02 105.53,79.87 105.4,80 105.05,80 104.92,79.87 104.92,79.02 104.8,78.89 104.45,78.89 104.32,79.02 104.32,79.84 104.33,79.84 104.21,79.96 103.85,79.96 103.85,79.96 103.72,79.83 103.72,79.02 103.59,78.89 102.84,78.89 v4(100.56,76.62) 99.23,76.62 98.73,76.12 98.73,74.83 v1(99.13,74.42)
MEM_CALRN0: length 2.3
  TOP w0.1: U1.J25 96.13,52.2 v1(95.72,52.62)
  BOTTOM w0.1: R302.1 95.94,52.84 v1(95.72,52.62) 95.54,52.44 R303.1
MEM_CALRP0: length 4.7
  TOP w0.1: U1.K25 95.35,52.14 95.66,51.83 96.2,51.83 96.45,52.08 96.45,52.48 96.56,52.59 v1(96.56,52.61)
  BOTTOM w0.1: R301.1 96.92,50.64 96.92,50.85 96.92,50.85 96.92,51.42 R303.2 96.53,52.57 v1(96.56,52.61)
MVDD_BOOT: length 4.5
  TOP w0.8: U701.1 151.12,97.92 D701.1 149.85,97.92 C705.1
MVDD_EN: length 16.2
  TOP w0.4: U701.7 146.3,100.47 C712.1 144.71,98.9 C711.1
  TOP w0.5: C711.1 143.34,98.59 142.95,98.2 140.15,98.2 136.4,101.95 136.4,103.31 Q842.3
MVDD_FB: length 5.2
  TOP w0.4: U701.6 145.57,101.73 R714.1 R710.1 R713.1 R711.1
MVDD_FB_TRACE: length 1.7
  TOP w0.5: NS700.2 139.26,100.61 138.26,101.61 R700.1
MVDD_LGATE: length 10.7
  TOP w0.8: R722.2 161.67,96.99 Q703.4
MVDD_LGATE_CTR: length 4.7
  TOP w0.8: R722.1 156.77,103.11 R715.1 154.05,103.11 153.95,103 U701.4
MVDD_PHASE: length 28
  TOP w0.503: L701.1 156.73,79.62 ; L701.1 153.35,81.05 ; L701.1 157.25,81.05 ; L701.1 156.09,82.91 ; L701.1 153.87,82.48 ; L701.1 153.87,79.62 ; L701.1 156.73,82.48 ; L701.1 155.3,83
  TOP w0.8: U701.8 146.68,98.2 147.26,97.62 C705.2 v2(147.26,95.7)
  BOTTOM w0.8: v2(153.85,91.5) 151.46,91.5 v2(147.26,95.7)
MVDD_SV: length 4.9
  TOP w0.4: R700.2 140.84,102.9 C713.1 142.06,103.5 142.74,103.5 143.22,103.98 R711.2
MVDD_UGATE: length 8.2
  TOP w0.8: Q701.4 152.65,92.96 155.4,95.71 155.4,98.36 R721.2
MVDD_UGATE_CTR: length 2.3
  TOP w0.8: R721.1 153.96,100.19 153.69,100.47 U701.2
MVDD_VCC: length 4.2
  TOP w0.8: R707.2 C703.1 146.68,104.66 U701.5
MVREFD_A: length 7.8
  TOP w0.2: v1(94.92,51) 95.32,51.4 U1.K26
  BOTTOM w0.3: v1(94.92,51) 95.4,50.52 95.4,49.77 95.94,49.23 95.94,49.02 C295.1 96.44,48.44 96.88,48 96.88,47.48 R292.1 96.85,47.42 97.17,47.1 97.41,47.1 v4(97.86,46.65) 98.16,46.65 98.85,45.95 98.9,45.95 R291.2
MVREFS_A: length 6.5
  TOP w0.3: U1.J26 96.15,51.39 v1(96.52,51.02)
  BOTTOM w0.3: C297.1 96.45,49.4 96.12,49.73 96.11,49.73 95.91,49.93 95.91,50.5 96.33,50.92 96.43,50.92 v1(96.52,51.02) ; R294.1 97.83,48.1 98,48.1 98.42,47.67 v4(98.6,47.67) 98.6,47.6 98.96,47.24 R293.2
  BOTTOM w0.4: R294.1 96.56,49.38 C297.1
NFB: length 18
  TOP w0.1: R4107.1 v3(157.15,25.8) ; v3(150.6,30.2) 145.08,30.2 144.55,29.67 R4108.1 145.1,29.09 145.25,29.24 Q4102.1
  BOTTOM w0.1: v3(150.6,30.2) 150.8,30 152.95,30 v3(157.15,25.8)
ODTA0: length 86
  TOP w0.097: v3(141.19,57.91) v4(141.19,56.99) 141.19,46.98 140.56,46.55 139.77,46.02 139.37,46.02 138.82,45.96 138.62,45.76 138.62,44.67 U202.K1
  TOP w0.1: v1(128.34,51.62) 128.34,51.88 128.21,52.01 125.45,52.01 125.32,52.13 125.32,54.93 v1(125.44,55.04)
  BOTTOM w0.097: v1(128.34,51.62) 128.31,51.59 127.01,51.59 126.88,51.47 126.88,51.28 127.01,51.16 128.29,51.16 128.38,51.06 128.38,50.93 128.29,50.84 126.98,50.84 126.89,50.75 126.89,50.63 126.98,50.54 128.25,50.54 128.34,50.45 128.34,50.33 128.25,50.24 127.16,50.24 127.08,50.15 127.08,50.03 127.16,49.94 128.25,49.94 128.34,49.85 128.34,48.73 128.47,48.6 128.49,48.6 128.64,48.35 128.65,48.33 128.67,48.3 128.72,48.22 128.72,48.19 129.02,47.74 129.03,47.73 129.03,47.23 128.93,47.13 128.93,46.93 129.03,46.83 129.03,46.63 128.93,46.53 128.93,46.33 129.02,46.24 129.02,46.09 128.93,46 128.78,46 128.58,45.8 128.59,45.79 128.59,45.26 128.46,45.14 127.93,45.14 127.82,45.03 127.82,44.89 127.93,44.79 128.97,44.79 129.06,44.87 129.06,45.68 129.15,45.77 129.27,45.77 129.36,45.68 129.36,44.85 129.48,44.73 129.6,44.73 129.72,44.85 129.72,45.51 129.81,45.59 129.94,45.59 130.03,45.51 130.03,45.38 130.15,45.26 130.22,45.26 130.35,45.13 130.35,45.05 130.24,44.94 130.1,44.94 130.03,44.86 130.03,44.7 130.15,44.58 130.34,44.58 130.59,44.83 130.72,44.83 130.81,44.74 130.81,44.62 130.52,44.32 130.52,44.21 131.01,43.72 132.26,43.72 132.56,44.02
  BOTTOM w0.1: R226.2 105.89,55.22 125.27,55.22 125.44,55.05 v1(125.44,55.04) 125.67,55.04 125.85,55.22 126.56,55.22 126.9,54.88 128.31,54.88 129.79,56.36 130.56,56.36 130.97,56.77 132.84,56.77 134.52,58.45 134.93,58.45 135.22,58.16 135.91,58.16 136.49,57.58 136.86,57.58 137.18,57.91 138.69,57.91 R225.1 140.06,57.53 R229.2 140.14,57.53 140.81,57.53 v3(141.19,57.91)
ODTA0_R: length 12.1
  TOP w0.2: v1(95.4,56.62) 95.24,56.78 95.18,56.78 94.65,57.3 94.65,57.5 U1.L18
  BOTTOM w0.1: v1(95.4,56.62) 95.85,56.17 98.5,56.17 98.61,56.29 99.32,56.29 99.42,56.19 99.42,55.78 99.53,55.69 101.78,55.69 101.99,55.9 101.99,55.92 102.41,56.35 104.76,56.35 R226.1
